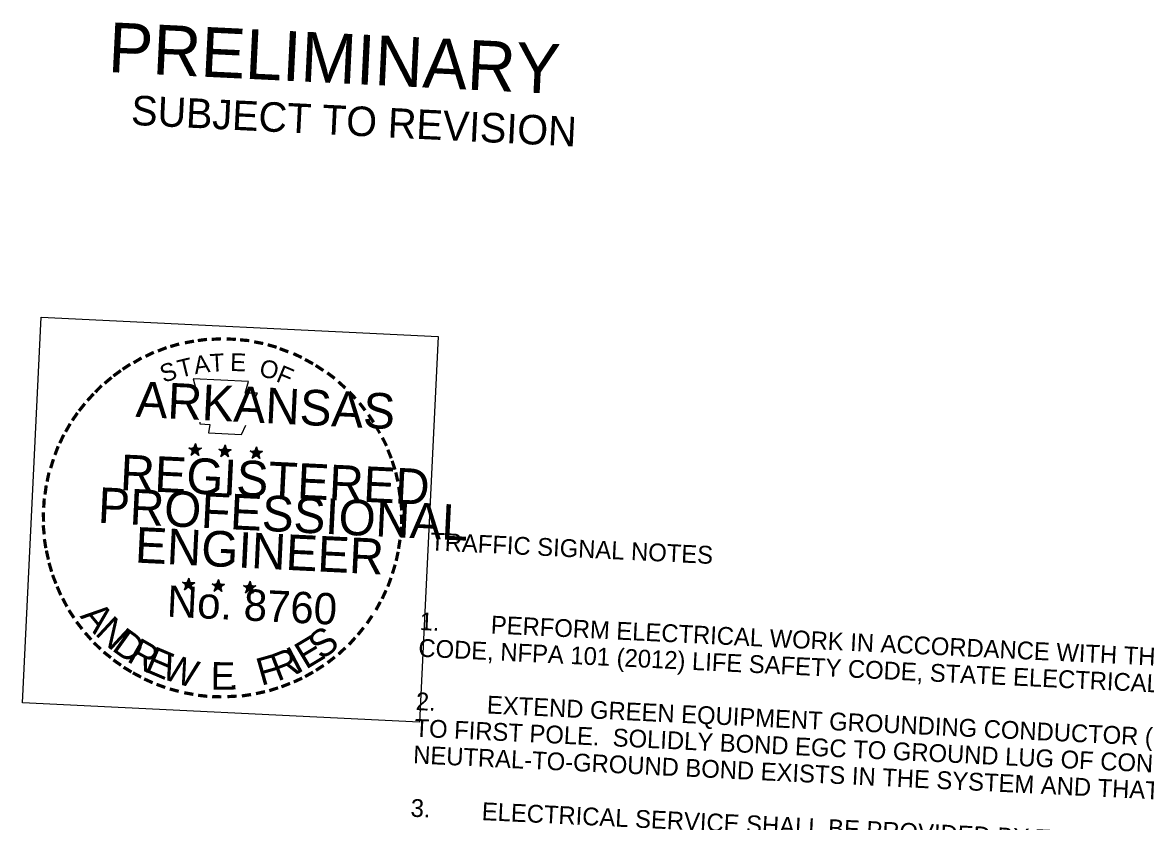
# Model space of a CAD drawing. Extents: x 669100 to 670534, y 743337 to 744379.
# Drawn here: x 669099.6 to 669257.3, y 743708.7 to 743820.9 of the extents above; entities that cross this region are included whole.
import ezdxf

# ---------------------------------------------------------------- set-up
doc = ezdxf.new("R2010")
doc.units = 0
for name, color, linetype in [('R_Border PE', 7, 'Continuous'), ('R_Border Prem', 7, 'Continuous'), ('R_Proposed Road Annot', 7, 'Continuous')]:
    doc.layers.add(name, color=color, linetype=linetype)

msp = doc.modelspace()

# ---------------------------------------------------------------- linework, layer by layer
at = {"layer": 'R_Border PE'}
for p, q in [((669123, 743761.18), (669123.86, 743760.87)), ((669123, 743761.18), (669123.64, 743761.1)), ((669123, 743761.18), (669123.64, 743761.05)), ((669123, 743761.18), (669123.61, 743761)), ((669123, 743761.18), (669123.61, 743760.9)), ((669123, 743761.18), (669123.58, 743760.86)), ((669123, 743761.18), (669123.58, 743760.81)), ((669123.29, 743760.14), (669123.86, 743760.87)), ((669123.29, 743760.14), (669123.6, 743760.83)), ((669123.9, 743761.79), (669123.75, 743761.17)), ((669123.9, 743761.79), (669123.77, 743761.15)), ((669123.9, 743761.79), (669123.85, 743761.17)), ((669123.86, 743760.87), (669123.9, 743761.79)), ((669124.74, 743761.1), (669123.86, 743760.87)), ((669124.37, 743760.09), (669123.86, 743760.87)), ((669123.9, 743761.79), (669124.04, 743761.13)), ((669123.9, 743761.79), (669124, 743761.16)), ((669123.9, 743761.79), (669123.95, 743761.16)), ((669124.74, 743761.1), (669123.97, 743761.09)), ((669124.74, 743761.1), (669124.01, 743761.01)), ((669124.74, 743761.1), (669124.01, 743760.96)), ((669124.37, 743760.09), (669124.05, 743760.83)), ((669124.37, 743760.09), (669124.11, 743760.85)), ((669124.74, 743761.1), (669124.18, 743760.9)), ((669124.74, 743761.1), (669124.23, 743760.87)), ((669124.74, 743761.1), (669124.26, 743760.85)), ((669127.17, 743760.98), (669128.03, 743760.66)), ((669127.17, 743760.98), (669127.81, 743760.9)), ((669127.17, 743760.98), (669127.81, 743760.85)), ((669127.17, 743760.98), (669127.78, 743760.8)), ((669127.17, 743760.98), (669127.75, 743760.7)), ((669127.17, 743760.98), (669127.75, 743760.65)), ((669127.17, 743760.98), (669127.75, 743760.6)), ((669128.07, 743761.59), (669127.92, 743760.97)), ((669128.07, 743761.59), (669127.94, 743760.94)), ((669128.07, 743761.59), (669127.99, 743760.97)), ((669128.03, 743760.66), (669128.07, 743761.59)), ((669128.91, 743760.9), (669128.03, 743760.66)), ((669128.07, 743761.59), (669128.21, 743760.93)), ((669128.07, 743761.59), (669128.17, 743760.96)), ((669128.07, 743761.59), (669128.09, 743760.96)), ((669128.91, 743760.9), (669128.14, 743760.88)), ((669128.91, 743760.9), (669128.18, 743760.81)), ((669128.91, 743760.9), (669128.18, 743760.76)), ((669128.91, 743760.9), (669128.35, 743760.7)), ((669128.91, 743760.9), (669128.4, 743760.67)), ((669128.91, 743760.9), (669128.43, 743760.64)), ((669132.49, 743761.32), (669132.31, 743760.73)), ((669132.49, 743761.32), (669132.36, 743760.7)), ((669132.49, 743761.32), (669132.41, 743760.7)), ((669132.44, 743760.42), (669132.49, 743761.32)), ((669132.49, 743761.32), (669132.63, 743760.69)), ((669132.49, 743761.32), (669132.58, 743760.69)), ((669132.49, 743761.32), (669132.51, 743760.72)), ((669123.29, 743760.14), (669123.62, 743760.75)), ((669123.29, 743760.14), (669123.67, 743760.73)), ((669123.29, 743760.14), (669123.85, 743760.67)), ((669123.29, 743760.14), (669123.74, 743760.65)), ((669123.29, 743760.14), (669123.87, 743760.59)), ((669124.37, 743760.09), (669123.84, 743760.59)), ((669124.37, 743760.09), (669123.85, 743760.67)), ((669124.37, 743760.09), (669123.94, 743760.64)), ((669124.37, 743760.09), (669124.02, 743760.73)), ((669127.47, 743759.94), (669128.03, 743760.66)), ((669127.47, 743759.94), (669127.77, 743760.63)), ((669127.47, 743759.94), (669127.79, 743760.55)), ((669127.47, 743759.94), (669127.84, 743760.52)), ((669127.47, 743759.94), (669128.02, 743760.46)), ((669127.47, 743759.94), (669127.91, 743760.44)), ((669127.47, 743759.94), (669128.04, 743760.39)), ((669128.54, 743759.89), (669128.01, 743760.39)), ((669128.54, 743759.89), (669128.02, 743760.46)), ((669128.54, 743759.89), (669128.03, 743760.66)), ((669128.54, 743759.89), (669128.11, 743760.43)), ((669128.54, 743759.89), (669128.19, 743760.53)), ((669128.54, 743759.89), (669128.22, 743760.63)), ((669128.54, 743759.89), (669128.28, 743760.65)), ((669131.58, 743760.74), (669132.44, 743760.42)), ((669131.58, 743760.74), (669132.23, 743760.64)), ((669131.58, 743760.74), (669132.2, 743760.59)), ((669131.58, 743760.74), (669132.2, 743760.56)), ((669131.58, 743760.74), (669132.17, 743760.46)), ((669131.58, 743760.74), (669132.17, 743760.41)), ((669131.58, 743760.74), (669132.17, 743760.36)), ((669131.86, 743759.7), (669132.44, 743760.42)), ((669131.86, 743759.7), (669132.19, 743760.39)), ((669131.86, 743759.7), (669132.21, 743760.31)), ((669131.86, 743759.7), (669132.26, 743760.28)), ((669131.86, 743759.7), (669132.43, 743760.22)), ((669131.86, 743759.7), (669132.33, 743760.2)), ((669131.86, 743759.7), (669132.46, 743760.15)), ((669132.93, 743759.65), (669132.43, 743760.22)), ((669132.93, 743759.65), (669132.43, 743760.15)), ((669133.33, 743760.66), (669132.44, 743760.42)), ((669132.93, 743759.65), (669132.44, 743760.42)), ((669132.93, 743759.65), (669132.53, 743760.19)), ((669133.33, 743760.66), (669132.56, 743760.64)), ((669133.33, 743760.66), (669132.6, 743760.57)), ((669133.33, 743760.66), (669132.6, 743760.52)), ((669132.93, 743759.65), (669132.61, 743760.29)), ((669132.93, 743759.65), (669132.64, 743760.39)), ((669132.93, 743759.65), (669132.69, 743760.39)), ((669133.33, 743760.66), (669132.77, 743760.46)), ((669133.33, 743760.66), (669132.8, 743760.43)), ((669133.33, 743760.66), (669132.84, 743760.41)), ((669122.08, 743742.28), (669122.94, 743741.96)), ((669122.08, 743742.28), (669122.72, 743742.17)), ((669122.08, 743742.28), (669122.7, 743742.13)), ((669122.08, 743742.28), (669122.69, 743742.1)), ((669122.08, 743742.28), (669122.66, 743742)), ((669122.08, 743742.28), (669122.66, 743741.95)), ((669122.08, 743742.28), (669122.66, 743741.9)), ((669122.35, 743741.24), (669122.94, 743741.96)), ((669122.35, 743741.24), (669122.69, 743741.93)), ((669122.98, 743742.86), (669122.8, 743742.27)), ((669122.98, 743742.86), (669122.85, 743742.24)), ((669122.98, 743742.86), (669122.9, 743742.24)), ((669122.94, 743741.96), (669122.98, 743742.86)), ((669123.83, 743742.2), (669122.94, 743741.96)), ((669123.43, 743741.19), (669122.94, 743741.96)), ((669122.98, 743742.86), (669123.13, 743742.23)), ((669122.98, 743742.86), (669123.08, 743742.23)), ((669122.98, 743742.86), (669123, 743742.24)), ((669123.83, 743742.2), (669123.05, 743742.18)), ((669123.83, 743742.2), (669123.09, 743742.11)), ((669123.83, 743742.2), (669123.09, 743742.06)), ((669123.43, 743741.19), (669123.11, 743741.93)), ((669123.43, 743741.19), (669123.19, 743741.93)), ((669123.83, 743742.2), (669123.24, 743742)), ((669123.83, 743742.2), (669123.29, 743741.97)), ((669123.83, 743742.2), (669123.34, 743741.92)), ((669126.25, 743742.08), (669127.11, 743741.76)), ((669126.25, 743742.08), (669126.87, 743741.97)), ((669126.25, 743742.08), (669126.87, 743741.92)), ((669126.25, 743742.08), (669126.86, 743741.9)), ((669126.25, 743742.08), (669126.83, 743741.8)), ((669126.25, 743742.08), (669126.83, 743741.75)), ((669126.25, 743742.08), (669126.83, 743741.7)), ((669127.15, 743742.66), (669126.97, 743742.07)), ((669127.15, 743742.66), (669127.02, 743742.04)), ((669127.15, 743742.66), (669127.07, 743742.04)), ((669127.11, 743741.76), (669127.15, 743742.66)), ((669127.97, 743741.99), (669127.11, 743741.76)), ((669127.15, 743742.66), (669127.27, 743742.03)), ((669127.15, 743742.66), (669127.25, 743742.03)), ((669127.15, 743742.66), (669127.17, 743742.03)), ((669127.97, 743741.99), (669127.22, 743741.98)), ((669127.97, 743741.99), (669127.26, 743741.9)), ((669127.97, 743741.99), (669127.26, 743741.85)), ((669127.97, 743741.99), (669127.41, 743741.8)), ((669127.97, 743741.99), (669127.46, 743741.77)), ((669127.97, 743741.99), (669127.51, 743741.72)), ((669131.57, 743742.42), (669131.39, 743741.8)), ((669131.57, 743742.42), (669131.44, 743741.8)), ((669131.57, 743742.42), (669131.49, 743741.8)), ((669131.53, 743741.52), (669131.57, 743742.42)), ((669131.57, 743742.42), (669131.69, 743741.79)), ((669131.57, 743742.42), (669131.66, 743741.79)), ((669131.57, 743742.42), (669131.59, 743741.79)), ((669122.35, 743741.24), (669122.71, 743741.83)), ((669122.35, 743741.24), (669122.75, 743741.8)), ((669122.35, 743741.24), (669122.93, 743741.76)), ((669122.35, 743741.24), (669122.83, 743741.74)), ((669122.35, 743741.24), (669122.92, 743741.69)), ((669123.43, 743741.19), (669122.9, 743741.69)), ((669123.43, 743741.19), (669122.93, 743741.74)), ((669123.43, 743741.19), (669123, 743741.74)), ((669123.43, 743741.19), (669123.11, 743741.83)), ((669126.52, 743741.04), (669127.11, 743741.76)), ((669126.52, 743741.04), (669126.86, 743741.72)), ((669126.52, 743741.04), (669126.88, 743741.62)), ((669126.52, 743741.04), (669126.92, 743741.6)), ((669126.52, 743741.04), (669127.1, 743741.56)), ((669126.52, 743741.04), (669127, 743741.54)), ((669126.52, 743741.04), (669127.09, 743741.49)), ((669127.6, 743740.99), (669127.07, 743741.49)), ((669127.6, 743740.99), (669127.1, 743741.54)), ((669127.6, 743740.99), (669127.11, 743741.76)), ((669127.6, 743740.99), (669127.17, 743741.53)), ((669127.6, 743740.99), (669127.28, 743741.73)), ((669127.6, 743740.99), (669127.28, 743741.63)), ((669127.6, 743740.99), (669127.36, 743741.72)), ((669130.67, 743741.84), (669131.53, 743741.52)), ((669130.67, 743741.84), (669131.29, 743741.73)), ((669130.67, 743741.84), (669131.28, 743741.68)), ((669130.67, 743741.84), (669131.26, 743741.64)), ((669130.67, 743741.84), (669131.25, 743741.56)), ((669130.67, 743741.84), (669131.22, 743741.49)), ((669130.67, 743741.84), (669131.22, 743741.44)), ((669130.94, 743740.8), (669131.53, 743741.52)), ((669130.94, 743740.8), (669131.25, 743741.49)), ((669130.94, 743740.8), (669131.27, 743741.38)), ((669130.94, 743740.8), (669131.34, 743741.36)), ((669130.94, 743740.8), (669131.42, 743741.3)), ((669130.94, 743740.8), (669131.49, 743741.3)), ((669130.94, 743740.8), (669131.51, 743741.25)), ((669132.01, 743740.75), (669131.49, 743741.3)), ((669132.01, 743740.75), (669131.49, 743741.22)), ((669132.39, 743741.76), (669131.53, 743741.52)), ((669132.01, 743740.75), (669131.53, 743741.52)), ((669132.01, 743740.75), (669131.59, 743741.29)), ((669132.39, 743741.76), (669131.64, 743741.74)), ((669132.01, 743740.75), (669131.67, 743741.36)), ((669132.39, 743741.76), (669131.68, 743741.66)), ((669132.39, 743741.76), (669131.68, 743741.61)), ((669132.01, 743740.75), (669131.7, 743741.49)), ((669132.01, 743740.75), (669131.75, 743741.49)), ((669132.39, 743741.76), (669131.83, 743741.56)), ((669132.39, 743741.76), (669131.88, 743741.5)), ((669132.39, 743741.76), (669131.9, 743741.48))]:
    msp.add_line(p, q, dxfattribs=at)
for points in [[(669123.59, 743770.87), (669124.14, 743768.76)], [(669132.24, 743768.14), (669132.63, 743768.83), (669130.9, 743768.86), (669131.36, 743770.49), (669123.59, 743770.87)], [(669124.52, 743764.76), (669124.51, 743764.54), (669125.91, 743764.42), (669125.72, 743763.25), (669130.39, 743763.03), (669130.96, 743764.33)], [(669123.9, 743761.79), (669124.37, 743760.09), (669123, 743761.18), (669124.74, 743761.1), (669123.29, 743760.14), (669123.9, 743761.79)], [(669128.07, 743761.59), (669128.54, 743759.89), (669127.17, 743760.98), (669128.91, 743760.9), (669127.47, 743759.94), (669128.07, 743761.59)], [(669132.49, 743761.32), (669132.93, 743759.65), (669131.58, 743760.74), (669133.33, 743760.66), (669131.86, 743759.7), (669132.49, 743761.32)], [(669122.98, 743742.86), (669123.43, 743741.19), (669122.08, 743742.28), (669123.83, 743742.2), (669122.35, 743741.24), (669122.98, 743742.86)], [(669127.15, 743742.66), (669127.6, 743740.99), (669126.25, 743742.08), (669127.97, 743741.99), (669126.52, 743741.04), (669127.15, 743742.66)], [(669131.57, 743742.42), (669132.01, 743740.75), (669130.67, 743741.84), (669132.39, 743741.76), (669130.94, 743740.8), (669131.57, 743742.42)]]:
    msp.add_lwpolyline(points, dxfattribs=at)
for centre, radius in [((669123.86, 743760.86), 0.431), ((669123.86, 743760.86), 0.39), ((669123.86, 743760.86), 0.361), ((669123.86, 743760.86), 0.332), ((669123.86, 743760.86), 0.289), ((669123.86, 743760.86), 0.269), ((669123.86, 743760.86), 0.248), ((669123.86, 743760.86), 0.213), ((669123.86, 743760.86), 0.187), ((669123.86, 743760.86), 0.155), ((669123.86, 743760.86), 0.124), ((669123.86, 743760.86), 0.0924), ((669123.86, 743760.86), 0.0741), ((669123.86, 743760.86), 0.036), ((669128.03, 743760.66), 0.431), ((669128.03, 743760.66), 0.39), ((669128.03, 743760.66), 0.361), ((669128.03, 743760.66), 0.332), ((669128.03, 743760.66), 0.289), ((669128.03, 743760.66), 0.269), ((669128.03, 743760.66), 0.248), ((669128.03, 743760.66), 0.213), ((669128.03, 743760.66), 0.187), ((669132.44, 743760.42), 0.431), ((669128.03, 743760.66), 0.155), ((669128.03, 743760.66), 0.124), ((669128.03, 743760.66), 0.0924), ((669128.03, 743760.66), 0.0741), ((669128.03, 743760.66), 0.036), ((669132.44, 743760.42), 0.39), ((669132.44, 743760.42), 0.361), ((669132.44, 743760.42), 0.332), ((669132.44, 743760.42), 0.289), ((669132.44, 743760.42), 0.269), ((669132.44, 743760.42), 0.248), ((669132.44, 743760.42), 0.213), ((669132.44, 743760.42), 0.187), ((669132.44, 743760.42), 0.155), ((669132.44, 743760.42), 0.124), ((669132.44, 743760.42), 0.0924), ((669132.44, 743760.42), 0.0741), ((669132.44, 743760.42), 0.036), ((669122.93, 743741.95), 0.431), ((669122.93, 743741.95), 0.39), ((669122.93, 743741.95), 0.361), ((669122.93, 743741.95), 0.332), ((669122.93, 743741.95), 0.289), ((669122.93, 743741.95), 0.269), ((669122.93, 743741.95), 0.248), ((669122.93, 743741.95), 0.213), ((669122.93, 743741.95), 0.187), ((669122.93, 743741.95), 0.155), ((669122.93, 743741.95), 0.124), ((669122.93, 743741.95), 0.0924), ((669122.93, 743741.95), 0.0741), ((669122.93, 743741.95), 0.036), ((669127.1, 743741.75), 0.431), ((669127.1, 743741.75), 0.39), ((669127.1, 743741.75), 0.361), ((669127.1, 743741.75), 0.332), ((669127.1, 743741.75), 0.289), ((669127.1, 743741.75), 0.269), ((669127.1, 743741.75), 0.248), ((669127.1, 743741.75), 0.213), ((669127.1, 743741.75), 0.187), ((669127.1, 743741.75), 0.155), ((669131.51, 743741.51), 0.431), ((669131.51, 743741.51), 0.39), ((669127.1, 743741.75), 0.124), ((669127.1, 743741.75), 0.0924), ((669127.1, 743741.75), 0.0741), ((669127.1, 743741.75), 0.036), ((669131.51, 743741.51), 0.361), ((669131.51, 743741.51), 0.332), ((669131.51, 743741.51), 0.289), ((669131.51, 743741.51), 0.269), ((669131.51, 743741.51), 0.248), ((669131.51, 743741.51), 0.213), ((669131.51, 743741.51), 0.187), ((669131.51, 743741.51), 0.155), ((669131.51, 743741.51), 0.124), ((669131.51, 743741.51), 0.0924), ((669131.51, 743741.51), 0.0741), ((669131.51, 743741.51), 0.036)]:
    msp.add_circle(centre, radius, dxfattribs=at)
at = {"layer": 'R_Border Prem'}
msp.add_lwpolyline([(669102.25, 743779.53), (669157.98, 743776.82), (669155.35, 743722.64), (669099.62, 743725.35)], close=True, dxfattribs=at)

# ---------------------------------------------------------------- texts
at = {"layer": 'R_Border PE'}
for s, height, rotation, p in [('-', 4, 7.4393, (669124.2, 743774.67)), ('-', 4, 3.1167, (669126.04, 743774.85)), ('-', 4, 357.4062, (669127.97, 743774.93)), ('-', 4, 21.5271, (669118.98, 743773.24)), ('-', 4, 16.396, (669120.58, 743773.84)), ('-', 4, 10.8501, (669122.48, 743774.35)), ('-', 4, 354.963, (669129.79, 743774.82)), ('-', 4, 349.3816, (669131.63, 743774.58)), ('-', 4, 344.4248, (669133.41, 743774.22)), ('-', 4, 339.5561, (669134.97, 743773.74)), ('-', 4, 31.2835, (669115.82, 743771.67)), ('-', 4, 26.0117, (669117.36, 743772.52)), ('T', 2.5, 13.6235, (669121.74, 743770.98)), ('A', 2.5, 8.4331, (669123.85, 743771.5)), ('T', 2.5, 3.2427, (669125.99, 743771.83)), ('E', 2.5, 358.0523, (669128.75, 743771.97)), ('O', 2.5, 347.6714, (669132.74, 743771.25)), ('-', 4, 335.075, (669136.79, 743773.1)), ('-', 4, 331.341, (669138.33, 743772.35)), ('-', 4, 36.1706, (669113.1, 743769.87)), ('-', 4, 33.4517, (669114.32, 743770.77)), ('S', 2.5, 18.8139, (669119.43, 743770.27)), ('F', 2.5, 337.2906, (669135.09, 743770.56)), ('-', 4, 326.8608, (669139.74, 743771.58)), ('-', 4, 323.0826, (669141.3, 743770.61)), ('-', 4, 40.1822, (669111.96, 743768.88)), ('ARKANSAS', 5, 357.2199, (669115.45, 743765.53)), ('-', 4, 317.7496, (669142.77, 743769.46)), ('-', 4, 47.8341, (669109.72, 743766.58)), ('-', 4, 45.643, (669110.77, 743767.73)), ('-', 4, 312.7985, (669144.21, 743768.16)), ('-', 4, 51.4524, (669108.62, 743765.21)), ('-', 4, 307.0996, (669145.57, 743766.72)), ('-', 4, 55.2906, (669107.74, 743763.93)), ('-', 4, 303.8721, (669146.79, 743765.16)), ('-', 4, 60.0913, (669106.89, 743762.44)), ('-', 3.5, 300.8952, (669147.95, 743763.68)), ('-', 4, 64.9942, (669106.16, 743760.95)), ('-', 4, 296.8883, (669148.67, 743762.11)), ('-', 4, 69.6144, (669105.54, 743759.4)), ('-', 4, 291.8827, (669149.4, 743760.55)), ('-', 4, 72.6809, (669104.98, 743757.63)), ('REGISTERED', 5, 357.2199, (669113.25, 743755.25)), ('-', 4, 287.7927, (669149.98, 743759.1)), ('-', 4, 78.4212, (669104.54, 743755.87)), ('-', 4, 282.3432, (669150.48, 743757.62)), ('-', 4, 82.4063, (669104.28, 743754.16)), ('PROFESSIONAL', 5, 357.2199, (669110.14, 743750.64)), ('-', 4, 277.7693, (669150.89, 743755.72)), ('-', 4, 86.2822, (669104.12, 743752.41)), ('-', 4, 273.8161, (669151.22, 743753.81)), ('-', 4, 91.4158, (669104.13, 743750.59)), ('-', 4, 271.55, (669151.28, 743751.98)), ('-', 4, 96.1679, (669104.23, 743748.93)), ('ENGINEER', 5, 357.2199, (669115.35, 743745.06)), ('-', 4, 267.1606, (669151.28, 743750.4)), ('-', 4, 98.9349, (669104.46, 743747.07)), ('-', 4, 260.7371, (669151.15, 743748.75)), ('-', 4, 102.6778, (669104.82, 743745.57)), ('-', 4, 106.3073, (669105.26, 743743.97)), ('-', 4, 258.2152, (669150.9, 743747.11)), ('-', 4, 252.9825, (669150.54, 743745.43)), ('-', 4, 111.2842, (669105.84, 743742.44)), ('-', 4, 250.088, (669150, 743743.65)), ('-', 4, 112.9488, (669106.51, 743740.86)), ('No. 8760', 4.4, 357.2199, (669119.83, 743737.46)), ('-', 4, 245.1086, (669149.37, 743742.01)), ('-', 4, 117.667, (669107.34, 743739.37)), ('A', 3.85, 309.6926, (669107.6, 743737.48)), ('-', 4, 241.8396, (669148.62, 743740.47)), ('-', 4, 123.1134, (669108.27, 743737.92)), ('N', 3.85, 317.0561, (669109.66, 743735)), ('-', 4, 236.2912, (669147.56, 743738.64)), ('-', 4, 127.938, (669109.36, 743736.47)), ('D', 3.85, 324.4196, (669112.01, 743732.81)), ('S', 3.85, 36.943, (669141.61, 743731.26)), ('-', 4, 231.0652, (669146.48, 743737.07)), ('-', 4, 131.4437, (669110.59, 743735.05)), ('R', 3.85, 330.3937, (669114.12, 743731.26)), ('E', 3.85, 31.1077, (669139.41, 743729.97)), ('-', 4, 228.4737, (669145.34, 743735.7)), ('-', 4, 136.1537, (669111.83, 743733.84)), ('-', 4, 141.8663, (669113.18, 743732.75)), ('E', 3.85, 336.9236, (669116.59, 743729.84)), ('W', 3.85, 342.7588, (669118.92, 743728.81)), ('R', 3.85, 21.2434, (669135.43, 743728.32)), ('I', 3.85, 27.7733, (669138.09, 743729.34)), ('-', 4, 222.9853, (669144.07, 743734.36)), ('-', 4, 145.3097, (669114.53, 743731.76)), ('E', 3.85, 359.5003, (669126.04, 743727.22)), ('F', 3.85, 15.825, (669133.14, 743727.72)), ('-', 4, 218.305, (669142.71, 743733.14)), ('-', 4, 148.7903, (669115.94, 743730.87)), ('-', 4, 151.8201, (669117.21, 743730.2)), ('-', 4, 209.469, (669139.88, 743731.13)), ('-', 4, 212.9563, (669141.28, 743732.04)), ('-', 4, 155.7811, (669118.75, 743729.48)), ('-', 4, 160.0182, (669120.42, 743728.87)), ('.', 3.85, 5.3355, (669128.59, 743727.16)), ('-', 4, 201.4715, (669136.85, 743729.6)), ('-', 4, 204.5768, (669138.47, 743730.32)), ('-', 4, 164.7754, (669122.2, 743728.38)), ('-', 4, 170.3354, (669124.11, 743728.02)), ('-', 4, 173.7382, (669125.98, 743727.77)), ('-', 4, 178.8117, (669127.83, 743727.73)), ('-', 4, 183.0366, (669129.86, 743727.84)), ('-', 4, 188.5057, (669131.72, 743728.07)), ('-', 4, 192.6942, (669133.57, 743728.48)), ('-', 4, 197.9383, (669135.27, 743729))]:
    msp.add_text(s, height=height, rotation=rotation, dxfattribs=at).set_placement(p)
at = {"layer": 'R_Border Prem'}
for s, height, p in [('PRELIMINARY', 7, (669111.55, 743813.96)), ('SUBJECT TO REVISION', 4.1502, (669114.81, 743806.54))]:
    msp.add_text(s, height=height, rotation=357.2008, dxfattribs=at).set_placement(p)
at = {"layer": 'R_Proposed Road Annot'}
for s, p in [(' TRAFFIC SIGNAL NOTES', (669155.9, 743746.82)), ('1.', (669155.35, 743735.58)), ('PERFORM ELECTRICAL WORK IN ACCORDANCE WITH THE CURRENT EDITIONS OF THE NFPA 70 (2014) NATIONAL ELECTRICAL ', (669165.34, 743735.1)), ('CODE, NFPA 101 (2012) LIFE SAFETY CODE, STATE ELECTRICAL CODE AND LOCAL ELECTRICAL CODE.', (669155.17, 743731.84)), ('2.', (669154.8, 743724.34)), ('EXTEND GREEN EQUIPMENT GROUNDING CONDUCTOR (EGC) FROM GROUND BAR AT MAIN BREAKER TO CONTROL PANEL AND ', (669164.79, 743723.86)), ('TO FIRST POLE.  SOLIDLY BOND EGC TO GROUND LUG OF CONTROL CABINET AND TO POLE GROUND.  ENSURE THAT ONLY ONE ', (669154.62, 743720.6)), ('NEUTRAL-TO-GROUND BOND EXISTS IN THE SYSTEM AND THAT IT IS AT THE MAIN BREAKER.', (669154.44, 743716.85)), ('3.', (669154.08, 743709.36)), ('ELECTRICAL SERVICE SHALL BE PROVIDED BY THE CITY TO A SERVICE POLE WITH EXTERNAL RAINTIGHT BREAKER (MAIN ', (669164.07, 743708.88))]:
    msp.add_text(s, height=2.5, rotation=357.2199, dxfattribs=at).set_placement(p)

doc.saveas('drawing.dxf')
